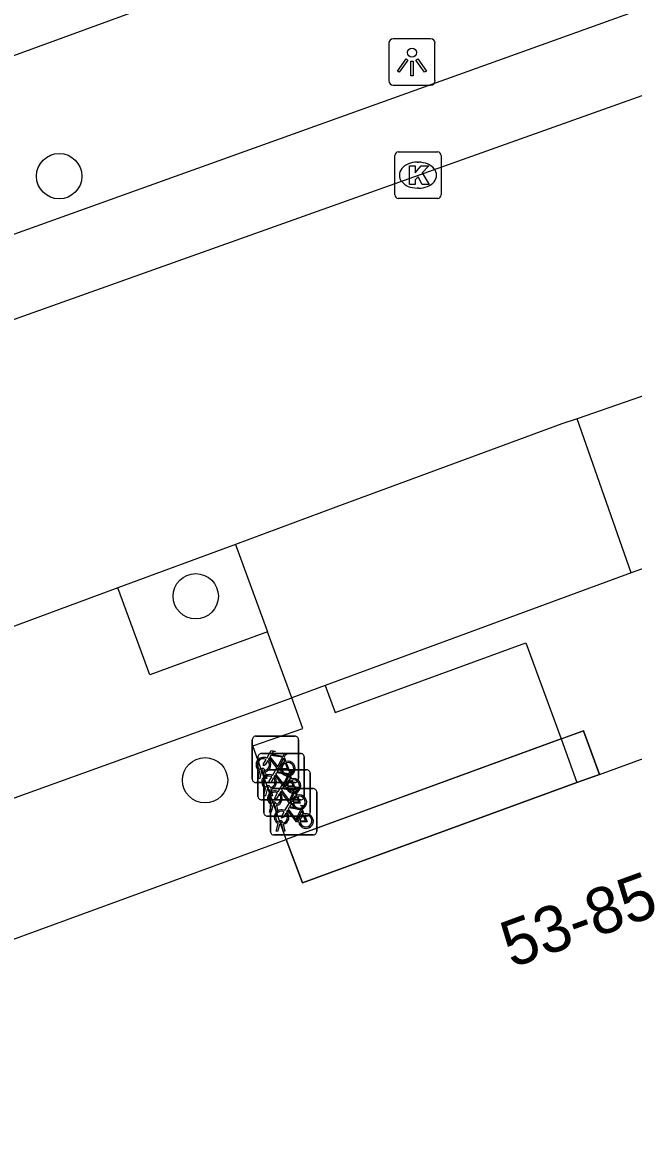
# Model space of a CAD drawing. Extents: x 162532 to 163264, y 381233 to 382042.
# Drawn here: x 162755.72 to 162768.9, y 381705.55 to 381729.86 of the extents above; entities that cross this region are included whole.
import ezdxf

# ---------------------------------------------------------------- set-up
doc = ezdxf.new("R2010")
doc.units = 0
for name, color, linetype in [('IMGEO_Boom', 7, 'Continuous'), ('IMGEO_Fietsenrek', 7, 'Continuous'), ('IMGEO_Kolk', 7, 'Continuous'), ('IMGEO_Lichtpunt', 7, 'Continuous'), ('IMGEO_Pand', 7, 'Continuous'), ('IMGEO_Pand_nummerreeks', 7, 'Continuous'), ('IMGEO_Pand_overbouw', 7, 'Continuous'), ('IMGEO_Rijbaan_lokaal_open', 7, 'Continuous'), ('IMGEO_Voetpad_open', 7, 'Continuous')]:
    doc.layers.add(name, color=color, linetype=linetype)

msp = doc.modelspace()

# ---------------------------------------------------------------- linework, layer by layer
at = {"layer": 'IMGEO_Boom'}
for centre in [(162756.514, 381726.547), (162759.459, 381717.482), (162759.66, 381713.512)]:
    msp.add_circle(centre, 0.489, dxfattribs=at)
at = {"layer": 'IMGEO_Fietsenrek'}
for p, q in [((162760.677, 381713.538), (162760.677, 381714.379)), ((162760.677, 381714.379), (162760.677, 381713.538)), ((162760.752, 381714.463), (162761.593, 381714.463)), ((162761.593, 381714.463), (162760.752, 381714.463)), ((162761.677, 381714.388), (162761.677, 381713.547)), ((162761.677, 381713.547), (162761.677, 381714.388)), ((162760.8, 381713.165), (162760.8, 381714.006)), ((162760.8, 381714.006), (162760.8, 381713.165)), ((162760.875, 381714.09), (162761.716, 381714.09)), ((162761.716, 381714.09), (162760.875, 381714.09)), ((162761.364, 381714.012), (162761.4, 381713.917)), ((162761.8, 381714.015), (162761.8, 381713.174)), ((162761.8, 381713.174), (162761.8, 381714.015)), ((162760.804, 381713.547), (162760.843, 381713.707)), ((162760.873, 381713.695), (162760.838, 381713.547)), ((162760.915, 381713.719), (162760.914, 381713.723)), ((162760.956, 381713.547), (162760.922, 381713.689)), ((162760.925, 381712.814), (162760.925, 381713.655)), ((162760.925, 381713.655), (162760.925, 381712.814)), ((162760.946, 381713.73), (162760.947, 381713.723)), ((162760.954, 381713.693), (162760.989, 381713.547)), ((162761, 381713.739), (162761.841, 381713.739)), ((162761.841, 381713.739), (162761, 381713.739)), ((162761.925, 381713.664), (162761.925, 381712.823)), ((162761.925, 381712.823), (162761.925, 381713.664)), ((162761.602, 381713.463), (162760.761, 381713.463)), ((162760.761, 381713.463), (162761.602, 381713.463)), ((162760.838, 381713.547), (162760.804, 381713.547)), ((162760.989, 381713.547), (162760.956, 381713.547)), ((162761.487, 381713.639), (162761.523, 381713.544)), ((162760.927, 381713.174), (162760.966, 381713.334)), ((162760.961, 381713.174), (162760.927, 381713.174)), ((162760.996, 381713.322), (162760.961, 381713.174)), ((162761.038, 381713.346), (162761.037, 381713.35)), ((162761.079, 381713.174), (162761.045, 381713.316)), ((162761.069, 381713.357), (162761.07, 381713.35)), ((162761.069, 381712.407), (162761.069, 381713.248)), ((162761.069, 381713.248), (162761.069, 381712.407)), ((162761.077, 381713.32), (162761.112, 381713.174)), ((162761.112, 381713.174), (162761.079, 381713.174)), ((162761.144, 381713.332), (162761.985, 381713.332)), ((162761.985, 381713.332), (162761.144, 381713.332)), ((162761.612, 381713.288), (162761.648, 381713.193)), ((162762.069, 381713.257), (162762.069, 381712.416)), ((162762.069, 381712.416), (162762.069, 381713.257)), ((162761.725, 381713.09), (162760.884, 381713.09)), ((162760.884, 381713.09), (162761.725, 381713.09)), ((162761.052, 381712.823), (162761.091, 381712.983)), ((162761.121, 381712.971), (162761.086, 381712.823)), ((162761.163, 381712.995), (162761.162, 381712.999)), ((162761.204, 381712.823), (162761.17, 381712.965)), ((162761.194, 381713.006), (162761.195, 381712.999)), ((162761.202, 381712.969), (162761.237, 381712.823)), ((162761.85, 381712.739), (162761.009, 381712.739)), ((162761.009, 381712.739), (162761.85, 381712.739)), ((162761.086, 381712.823), (162761.052, 381712.823)), ((162761.237, 381712.823), (162761.204, 381712.823)), ((162761.756, 381712.881), (162761.792, 381712.786)), ((162761.196, 381712.416), (162761.235, 381712.576)), ((162761.265, 381712.564), (162761.23, 381712.416)), ((162761.307, 381712.588), (162761.306, 381712.592)), ((162761.348, 381712.416), (162761.314, 381712.558)), ((162761.338, 381712.599), (162761.339, 381712.592)), ((162761.346, 381712.562), (162761.381, 381712.416)), ((162761.994, 381712.332), (162761.153, 381712.332)), ((162761.153, 381712.332), (162761.994, 381712.332)), ((162761.23, 381712.416), (162761.196, 381712.416)), ((162761.381, 381712.416), (162761.348, 381712.416))]:
    msp.add_line(p, q, dxfattribs=at)
for points in [[(162760.99, 381713.989), (162761.085, 381714.153), (162761.171, 381714.139), (162761.173, 381714.13), (162761.117, 381714.119), (162761.09, 381714.074), (162761.346, 381714.033)], [(162761.011, 381713.937), (162760.959, 381713.847), (162760.919, 381713.822), (162760.92, 381713.869), (162760.975, 381713.963)], [(162761.286, 381713.745), (162761.236, 381713.745), (162761.045, 381713.996), (162761.026, 381713.964)], [(162761.333, 381714.008), (162761.076, 381714.049), (162761.059, 381714.02), (162761.226, 381713.8), (162761.333, 381714.008)], [(162761.381, 381713.91), (162761.351, 381713.987), (162761.242, 381713.769), (162761.285, 381713.769)], [(162761.346, 381714.033), (162761.371, 381714.082), (162761.365, 381714.086), (162761.342, 381714.09), (162761.33, 381714.097), (162761.329, 381714.1), (162761.331, 381714.105), (162761.426, 381714.09), (162761.428, 381714.08), (162761.418, 381714.067), (162761.406, 381714.061), (162761.392, 381714.067), (162761.364, 381714.012)], [(162761.113, 381713.616), (162761.208, 381713.78), (162761.294, 381713.766), (162761.296, 381713.757), (162761.24, 381713.746), (162761.213, 381713.701), (162761.469, 381713.66)], [(162761.456, 381713.635), (162761.199, 381713.676), (162761.182, 381713.647), (162761.349, 381713.427), (162761.456, 381713.635)], [(162761.315, 381713.769), (162761.435, 381713.768), (162761.391, 381713.882)], [(162761.411, 381713.889), (162761.466, 381713.744), (162761.316, 381713.744)], [(162761.469, 381713.66), (162761.494, 381713.709), (162761.488, 381713.713), (162761.465, 381713.717), (162761.453, 381713.724), (162761.452, 381713.727), (162761.454, 381713.732), (162761.549, 381713.717), (162761.551, 381713.707), (162761.541, 381713.694), (162761.529, 381713.688), (162761.515, 381713.694), (162761.487, 381713.639)], [(162761.134, 381713.564), (162761.082, 381713.474), (162761.042, 381713.449), (162761.043, 381713.496), (162761.098, 381713.59)], [(162761.409, 381713.372), (162761.359, 381713.372), (162761.168, 381713.623), (162761.149, 381713.591)], [(162761.238, 381713.265), (162761.333, 381713.429), (162761.419, 381713.415), (162761.421, 381713.406), (162761.365, 381713.395), (162761.338, 381713.35), (162761.594, 381713.309)], [(162761.504, 381713.537), (162761.474, 381713.614), (162761.365, 381713.396), (162761.408, 381713.396)], [(162761.438, 381713.396), (162761.558, 381713.395), (162761.514, 381713.509)], [(162761.534, 381713.516), (162761.589, 381713.371), (162761.439, 381713.371)], [(162761.259, 381713.213), (162761.207, 381713.123), (162761.167, 381713.098), (162761.168, 381713.145), (162761.223, 381713.239)], [(162761.534, 381713.021), (162761.484, 381713.021), (162761.293, 381713.272), (162761.274, 381713.24)], [(162761.581, 381713.284), (162761.324, 381713.325), (162761.307, 381713.296), (162761.474, 381713.076), (162761.581, 381713.284)], [(162761.629, 381713.186), (162761.599, 381713.263), (162761.49, 381713.045), (162761.533, 381713.045)], [(162761.659, 381713.165), (162761.714, 381713.02), (162761.564, 381713.02)], [(162761.594, 381713.309), (162761.619, 381713.358), (162761.613, 381713.362), (162761.59, 381713.366), (162761.578, 381713.373), (162761.577, 381713.376), (162761.579, 381713.381), (162761.674, 381713.366), (162761.676, 381713.356), (162761.666, 381713.343), (162761.654, 381713.337), (162761.64, 381713.343), (162761.612, 381713.288)], [(162761.382, 381712.858), (162761.477, 381713.022), (162761.563, 381713.008), (162761.565, 381712.999), (162761.509, 381712.988), (162761.482, 381712.943), (162761.738, 381712.902)], [(162761.563, 381713.045), (162761.683, 381713.044), (162761.639, 381713.158)], [(162761.738, 381712.902), (162761.763, 381712.951), (162761.757, 381712.955), (162761.734, 381712.959), (162761.722, 381712.966), (162761.721, 381712.969), (162761.723, 381712.974), (162761.818, 381712.959), (162761.82, 381712.949), (162761.81, 381712.936), (162761.798, 381712.93), (162761.784, 381712.936), (162761.756, 381712.881)], [(162761.403, 381712.806), (162761.351, 381712.716), (162761.311, 381712.691), (162761.312, 381712.738), (162761.367, 381712.832)], [(162761.678, 381712.614), (162761.628, 381712.614), (162761.437, 381712.865), (162761.418, 381712.833)], [(162761.725, 381712.877), (162761.468, 381712.918), (162761.451, 381712.889), (162761.618, 381712.669), (162761.725, 381712.877)], [(162761.773, 381712.779), (162761.743, 381712.856), (162761.634, 381712.638), (162761.677, 381712.638)], [(162761.707, 381712.638), (162761.827, 381712.637), (162761.783, 381712.751)], [(162761.803, 381712.758), (162761.858, 381712.613), (162761.708, 381712.613)]]:
    msp.add_lwpolyline(points, dxfattribs=at)
for centre, radius, start, end in [((162760.755, 381714.385), 0.0779, 92.4484, 184.2845), ((162760.755, 381714.385), 0.0779, 92.4484, 184.2845), ((162761.599, 381714.385), 0.0779, 2.4484, 94.2845), ((162761.599, 381714.385), 0.0779, 2.4484, 94.2845), ((162760.917, 381713.848), 0.159, 62.6766, 242.1369), ((162760.917, 381713.848), 0.129, 63.3192, 238.903), ((162760.878, 381714.012), 0.0779, 92.4484, 184.2845), ((162760.878, 381714.012), 0.0779, 92.4484, 184.2845), ((162760.917, 381713.848), 0.129, 283.6043, 43.4302), ((162760.917, 381713.848), 0.159, 283.5766, 46.6042), ((162761.444, 381713.764), 0.159, 113.3408, 178.3217), ((162761.444, 381713.764), 0.159, 187.0065, 105.7708), ((162761.444, 381713.764), 0.129, 188.6715, 104.5883), ((162761.722, 381714.012), 0.0779, 2.4484, 94.2845), ((162761.722, 381714.012), 0.0779, 2.4484, 94.2845), ((162760.897, 381713.719), 0.0499, 12.8025, 158.6934), ((162760.917, 381713.848), 0.159, 253.9967, 271.7867), ((162760.897, 381713.719), 0.0174, 12.8025, 163.4502), ((162760.917, 381713.848), 0.129, 253.415, 269.0204), ((162761.003, 381713.661), 0.0779, 92.4484, 184.2845), ((162761.003, 381713.661), 0.0779, 92.4484, 184.2845), ((162761.444, 381713.764), 0.129, 113.923, 177.9556), ((162761.847, 381713.661), 0.0779, 2.4484, 94.2845), ((162761.847, 381713.661), 0.0779, 2.4484, 94.2845), ((162760.755, 381713.541), 0.0779, 182.4484, 274.2845), ((162760.755, 381713.541), 0.0779, 182.4484, 274.2845), ((162761.04, 381713.475), 0.159, 62.6766, 242.1369), ((162761.04, 381713.475), 0.129, 63.3192, 238.903), ((162761.04, 381713.475), 0.129, 283.6043, 43.4302), ((162761.04, 381713.475), 0.159, 283.5766, 46.6042), ((162761.567, 381713.391), 0.159, 113.3408, 178.3217), ((162761.567, 381713.391), 0.159, 187.0065, 105.7708), ((162761.567, 381713.391), 0.129, 113.923, 177.9556), ((162761.567, 381713.391), 0.129, 188.6715, 104.5883), ((162761.599, 381713.541), 0.0779, 272.4484, 4.2845), ((162761.599, 381713.541), 0.0779, 272.4484, 4.2845), ((162760.878, 381713.168), 0.0779, 182.4484, 274.2845), ((162760.878, 381713.168), 0.0779, 182.4484, 274.2845), ((162761.02, 381713.346), 0.0499, 12.8025, 158.6934), ((162761.04, 381713.475), 0.159, 253.9967, 271.7867), ((162761.02, 381713.346), 0.0174, 12.8025, 163.4502), ((162761.04, 381713.475), 0.129, 253.415, 269.0204), ((162761.165, 381713.124), 0.159, 62.6766, 242.1369), ((162761.165, 381713.124), 0.129, 63.3192, 238.903), ((162761.147, 381713.254), 0.0779, 92.4484, 184.2845), ((162761.147, 381713.254), 0.0779, 92.4484, 184.2845), ((162761.165, 381713.124), 0.129, 283.6043, 43.4302), ((162761.165, 381713.124), 0.159, 283.5766, 46.6042), ((162761.692, 381713.04), 0.159, 113.3408, 178.3217), ((162761.692, 381713.04), 0.159, 187.0065, 105.7708), ((162761.692, 381713.04), 0.129, 188.6715, 104.5883), ((162761.722, 381713.168), 0.0779, 272.4484, 4.2845), ((162761.722, 381713.168), 0.0779, 272.4484, 4.2845), ((162761.991, 381713.254), 0.0779, 2.4484, 94.2845), ((162761.991, 381713.254), 0.0779, 2.4484, 94.2845), ((162761.145, 381712.995), 0.0499, 12.8025, 158.6934), ((162761.165, 381713.124), 0.159, 253.9967, 271.7867), ((162761.145, 381712.995), 0.0174, 12.8025, 163.4502), ((162761.165, 381713.124), 0.129, 253.415, 269.0204), ((162761.692, 381713.04), 0.129, 113.923, 177.9556), ((162761.003, 381712.817), 0.0779, 182.4484, 274.2845), ((162761.003, 381712.817), 0.0779, 182.4484, 274.2845), ((162761.309, 381712.717), 0.159, 62.6766, 242.1369), ((162761.309, 381712.717), 0.129, 63.3192, 238.903), ((162761.309, 381712.717), 0.129, 283.6043, 43.4302), ((162761.309, 381712.717), 0.159, 283.5766, 46.6042), ((162761.836, 381712.633), 0.159, 113.3408, 178.3217), ((162761.836, 381712.633), 0.159, 187.0065, 105.7708), ((162761.836, 381712.633), 0.129, 113.923, 177.9556), ((162761.836, 381712.633), 0.129, 188.6715, 104.5883), ((162761.847, 381712.817), 0.0779, 272.4484, 4.2845), ((162761.847, 381712.817), 0.0779, 272.4484, 4.2845), ((162761.289, 381712.588), 0.0499, 12.8025, 158.6934), ((162761.309, 381712.717), 0.159, 253.9967, 271.7867), ((162761.289, 381712.588), 0.0174, 12.8025, 163.4502), ((162761.309, 381712.717), 0.129, 253.415, 269.0204), ((162761.147, 381712.41), 0.0779, 182.4484, 274.2845), ((162761.147, 381712.41), 0.0779, 182.4484, 274.2845), ((162761.991, 381712.41), 0.0779, 272.4484, 4.2845), ((162761.991, 381712.41), 0.0779, 272.4484, 4.2845)]:
    msp.add_arc(centre, radius, start, end, dxfattribs=at)
at = {"layer": 'IMGEO_Kolk'}
for p, q in [((162763.824, 381727.069), (162764.676, 381727.069)), ((162763.749, 381726.143), (162763.749, 381726.995)), ((162764.237, 381726.849), (162764.262, 381726.849)), ((162764.75, 381726.995), (162764.75, 381726.143)), ((162764.676, 381726.069), (162763.824, 381726.069)), ((162764.26, 381726.289), (162764.235, 381726.289))]:
    msp.add_line(p, q, dxfattribs=at)
for points in [[(162763.824, 381727.069), (162764.676, 381727.069)], [(162763.749, 381726.143), (162763.749, 381726.995)], [(162764.75, 381726.995), (162764.75, 381726.143)], [(162764.07, 381726.769), (162764.193, 381726.769), (162764.193, 381726.618), (162764.323, 381726.769), (162764.487, 381726.769), (162764.341, 381726.618), (162764.494, 381726.369), (162764.342, 381726.369), (162764.257, 381726.533), (162764.193, 381726.466), (162764.193, 381726.369), (162764.07, 381726.369), (162764.07, 381726.769)], [(162764.676, 381726.069), (162763.824, 381726.069)]]:
    msp.add_lwpolyline(points, dxfattribs=at)
for centre, start, end in [((162763.826, 381726.993), 91.552, 178.448), ((162763.826, 381726.993), 91.552, 178.448), ((162764.674, 381726.993), 1.552, 88.448), ((162764.674, 381726.993), 1.552, 88.448), ((162763.826, 381726.145), 181.552, 268.448), ((162763.826, 381726.145), 181.552, 268.448), ((162764.674, 381726.145), 271.552, 358.448), ((162764.674, 381726.145), 271.552, 358.448)]:
    msp.add_arc(centre, 0.0765, start, end, dxfattribs=at)
for centre, major_axis, ratio, start_param, end_param in [((162764.236, 381726.569), (-0.387, 0.002), 0.722429, 4.712389, 7.853982), ((162764.261, 381726.569), (-0.39, 0.002), 0.717154, 1.570796, 4.712389)]:
    msp.add_ellipse(centre, major_axis=major_axis, ratio=ratio, start_param=start_param, end_param=end_param, dxfattribs=at)
at = {"layer": 'IMGEO_Lichtpunt'}
for p, q in [((162764.524, 381729.51), (162763.716, 381729.51)), ((162764.524, 381729.51), (162763.716, 381729.51)), ((162763.622, 381729.415), (162763.622, 381728.608)), ((162763.622, 381729.415), (162763.622, 381728.608)), ((162764.618, 381728.608), (162764.618, 381729.415)), ((162764.618, 381728.608), (162764.618, 381729.415)), ((162763.716, 381728.514), (162764.524, 381728.514)), ((162763.716, 381728.514), (162764.524, 381728.514))]:
    msp.add_line(p, q, dxfattribs=at)
for points in [[(162763.996, 381729.079), (162764.035, 381729.051), (162763.847, 381728.789), (162763.809, 381728.816), (162763.996, 381729.079)], [(162764.098, 381729.031), (162764.145, 381729.031), (162764.145, 381728.709), (162764.098, 381728.709), (162764.098, 381729.031)], [(162764.208, 381729.051), (162764.246, 381729.078), (162764.433, 381728.816), (162764.394, 381728.788), (162764.208, 381729.051)]]:
    msp.add_lwpolyline(points, dxfattribs=at)
msp.add_circle((162764.121, 381729.213), 0.0994, dxfattribs=at)
for centre, start, end in [((162763.716, 381729.415), 90, 180), ((162763.716, 381729.415), 90, 180), ((162764.524, 381729.415), 0, 90), ((162764.524, 381729.415), 0, 90), ((162763.716, 381728.608), 180, 270), ((162763.716, 381728.608), 180, 270), ((162764.524, 381728.608), 270, 0), ((162764.524, 381728.608), 270, 360)]:
    msp.add_arc(centre, 0.0946, start, end, dxfattribs=at)
at = {"layer": 'IMGEO_Pand'}
for points in [[(162768.163, 381713.64), (162773.695, 381715.655), (162773.351, 381716.588), (162780.839, 381719.349), (162788.324, 381698.788), (162787.479, 381698.48), (162788.396, 381695.983), (162784.239, 381694.45), (162784.373, 381694.084), (162776.989, 381691.384), (162775.198, 381696.284), (162778.03, 381697.323), (162775.358, 381704.61), (162773.427, 381703.898), (162759.719, 381698.841)], [(162767.679, 381713.464), (162761.761, 381711.299), (162761.409, 381712.234)], [(162768.163, 381713.64), (162767.679, 381713.464)], [(162734.977, 381702.577), (162740.13, 381704.457), (162740.453, 381703.623), (162741.985, 381704.181), (162741.677, 381705.026), (162746.839, 381706.907), (162747.158, 381706.066), (162748.708, 381706.633), (162748.399, 381707.478), (162753.556, 381709.363), (162753.844, 381708.508), (162755.423, 381709.086), (162755.114, 381709.931), (162761.409, 381712.234)]]:
    msp.add_lwpolyline(points, dxfattribs=at)
at = {"layer": 'IMGEO_Pand_overbouw'}
msp.add_lwpolyline([(162761.409, 381712.234), (162761.761, 381711.299), (162767.679, 381713.464), (162768.163, 381713.64), (162767.817, 381714.579)], close=True, dxfattribs=at)
at = {"layer": 'IMGEO_Rijbaan_lokaal_open'}
for points in [[(162745.077, 381719.704), (162747.636, 381720.644), (162766.566, 381727.391), (162786.892, 381734.638)], [(162770.249, 381722.202), (162767.683, 381721.314)], [(162767.683, 381721.314), (162767.355, 381721.2), (162766.087, 381720.739), (162762.482, 381719.404), (162760.315, 381718.601)], [(162760.315, 381718.601), (162757.781, 381717.663)], [(162757.781, 381717.663), (162751.373, 381715.289), (162748.15, 381714.148)]]:
    msp.add_lwpolyline(points, dxfattribs=at)
at = {"layer": 'IMGEO_Voetpad_open'}
for points in [[(162785.552, 381739.818), (162784.481, 381739.514), (162784.426, 381739.706), (162746.424, 381725.819), (162739.44, 381723.44)], [(162747.28, 381722.33), (162783.644, 381735.394)], [(162778.489, 381721.436), (162768.851, 381717.989)], [(162768.851, 381717.989), (162767.683, 381721.314)], [(162760.315, 381718.601), (162761.006, 381716.713)], [(162768.851, 381717.989), (162762.252, 381715.555)], [(162761.006, 381716.713), (162758.468, 381715.785), (162757.781, 381717.663)], [(162761.529, 381715.288), (162761.006, 381716.713)], [(162762.252, 381715.555), (162762.466, 381714.975), (162766.58, 381716.476), (162767.337, 381714.403)], [(162762.252, 381715.555), (162761.529, 381715.288)], [(162734.45, 381704.133), (162734.235, 381704.704), (162739.121, 381707.042), (162745.777, 381709.607), (162761.529, 381715.288)], [(162761.409, 381712.234), (162760.693, 381714.258), (162761.766, 381714.631), (162761.529, 381715.288)], [(162767.337, 381714.403), (162761.719, 381712.348), (162761.409, 381712.234)], [(162767.337, 381714.403), (162767.817, 381714.579), (162768.163, 381713.64)], [(162767.337, 381714.403), (162767.679, 381713.464)]]:
    msp.add_lwpolyline(points, dxfattribs=at)

# ---------------------------------------------------------------- texts
at = {"layer": 'IMGEO_Pand_nummerreeks'}
msp.add_text('53-85', height=1, rotation=20.0504, dxfattribs=at).set_placement((162766.274, 381709.455))

doc.saveas('drawing.dxf')
